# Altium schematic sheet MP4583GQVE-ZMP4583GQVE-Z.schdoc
size 127 x 101 mm
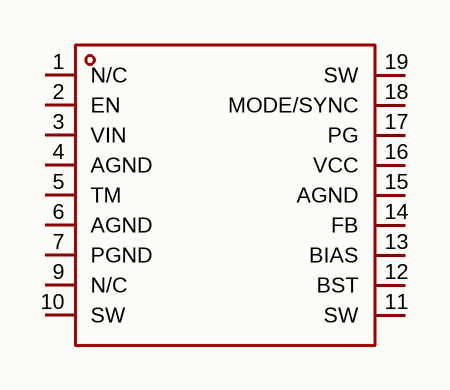
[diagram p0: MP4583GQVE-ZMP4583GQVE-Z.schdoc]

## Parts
U?  mp4583gqve-z  [QFN-19_L5.0-W3.0_CD4583GQVE]  (value not drawn)

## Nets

Not connected (* = marked no-connect by the designer): U? 1(N/C) 2(EN) 3(VIN) 4(AGND) 5(TM) 6(AGND) 7(PGND) 9(N/C) 10(SW) 11(SW) 12(BST) 13(BIAS) 14(FB) 15(AGND) 16(VCC) 17(PG) 18(MODE/SYNC) 19(SW)

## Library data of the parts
U? = mp4583gqve-z: 功能类型:降压型;工作电压:4.5V~100V;输出电压:800mV~35V;输出电流:3A;输出类型:可调;; Manufacturer: MPS(芯源); AddInBom: yes; ModelId: f9a696edf16e4987a7f3aab6e8a0affe; ModelTransform: 197.6374,118.8974,0,0,0,0,0.001,-0.002,0; Function: 降压型; Output Current: 3A; Frequency - Switching: 400kHz; Synchronous Rectifier: 是; Number of Outputs: 1; Topology: 降压式; Quiescent Current: 8uA; Switch tube (built-in/external): 内置; Output Type: 可调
